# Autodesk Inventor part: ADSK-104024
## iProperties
Shininess: 0.0
Created: 2000-09
Part Number: ADSK-104024
Document SubType Name: Modeling
Stock Number: ADSK-104024
Density: 1 g/cm^3
Density: 0.0
Volumn: 0.0
Area: 0.0
PropertySet Name: Model Information
Control State: 0
Master: False
Checked Out: False
Author: gao
